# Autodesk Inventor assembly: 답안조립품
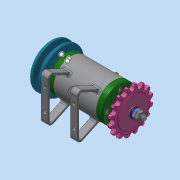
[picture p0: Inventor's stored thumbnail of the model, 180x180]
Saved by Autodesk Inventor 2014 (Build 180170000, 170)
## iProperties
Created: 2021-12
Part Number: 답안조립품
Document SubType Name: Assembly
Designer: dg
Author: dg
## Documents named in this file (16)
- C:\Users\dg\Desktop\711206V1011\답안조립품.iam
- C:\Users\dg\Desktop\711206V1011\본체.ipt
- C:\Users\dg\Desktop\711206V1011\V벨트풀리.ipt
- C:\Users\dg\Desktop\711206V1011\너트 M8.ipt
- C:\Users\dg\Desktop\711206V1011\니플 M6 x 0.75.ipt
- C:\Users\dg\Desktop\711206V1011\베어링 6002.ipt
- C:\Users\dg\Desktop\711206V1011\볼트 M4 x 12.ipt
- C:\Users\dg\Desktop\711206V1011\볼트 M6 x 8.ipt
- C:\Users\dg\Desktop\711206V1011\스프로킷.ipt
- C:\Users\dg\Desktop\711206V1011\스프링와셔 8.ipt
- C:\Users\dg\Desktop\711206V1011\오일 실 15 x 25 x 7.ipt
- C:\Users\dg\Desktop\711206V1011\와셔 6 x 11.5.ipt
- C:\Users\dg\Desktop\711206V1011\와셔 8 x 17.ipt
- C:\Users\dg\Desktop\711206V1011\축.ipt
- C:\Users\dg\Desktop\711206V1011\커버.ipt
- C:\Users\dg\Desktop\711206V1011\키 3 x 3.ipt
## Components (11 placed, 3 different names)
1. V벨트풀리:1
2. KS B 2023 6002 - 15 x 32 x 9:1
3. KS B 2023 6002 - 15 x 32 x 9:2
4. ISO 4762 M4 x 12:1
5. ISO 4762 M4 x 12:3
6. ISO 4762 M4 x 12:4
7. ISO 4762 M4 x 12:5
8. ISO 4762 M4 x 12:2
9. ISO 4762 M4 x 12:6
10. ISO 4762 M4 x 12:7
11. ISO 4762 M4 x 12:8
